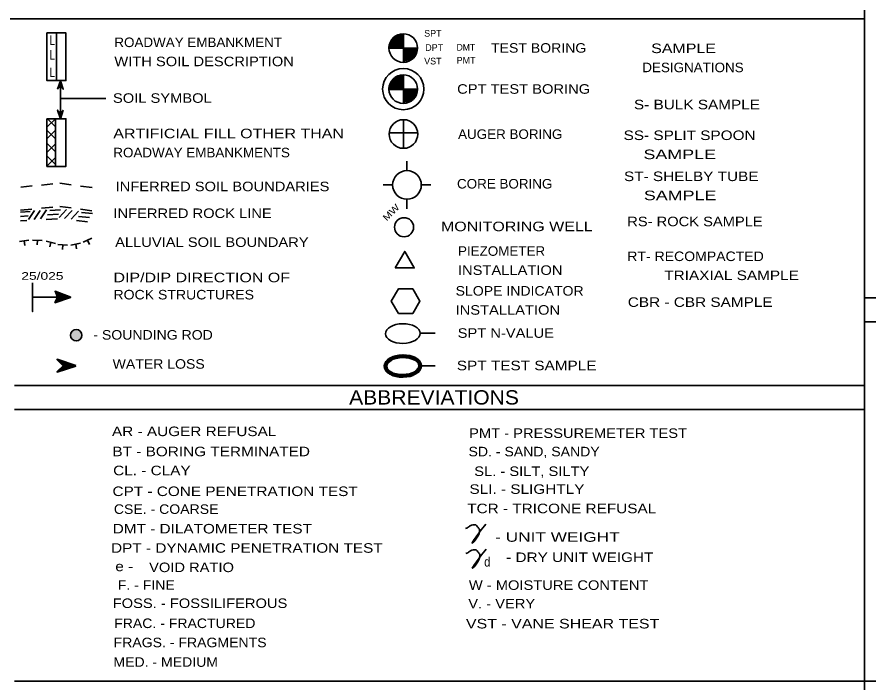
# Model space of a CAD drawing. Extents: x 2137492.6 to 2137529.1, y 2137475.8 to 2137563.
# Drawn here: x 2137501.9 to 2137510.82, y 2137544.13 to 2137551.11 of the extents above; entities that cross this region are included whole.
import ezdxf
from ezdxf.enums import TextEntityAlignment as Align

# ---------------------------------------------------------------- set-up
doc = ezdxf.new("R2010")
doc.units = 0
doc.header["$LTSCALE"] = 0.04
doc.linetypes.add('MEDIUM_DASHED', pattern=[4.5, 3, -1.5])
doc.layers.add('1', color=7, linetype='Continuous', lineweight=35)
doc.layers.add('10', color=7, linetype='Continuous', lineweight=40)

msp = doc.modelspace()

# ---------------------------------------------------------------- hatches: boundary and pattern name
at = {"layer": '1'}
for points in [[(2137502.32, 2137550.353), (2137502.35, 2137550.443), (2137502.38, 2137550.353), (2137502.35, 2137550.383)], [(2137502.38, 2137550.135), (2137502.35, 2137550.045), (2137502.32, 2137550.135), (2137502.35, 2137550.105)], [(2137502.57616, 2137547.77592, 1), (2137502.45616, 2137547.77592, 1)]]:
    msp.add_hatch(color=256, dxfattribs=at).paths.add_polyline_path(points)

# ---------------------------------------------------------------- linework, layer by layer
for p, q in [((2137510.771, 2137558.218), (2137510.771, 2137539.727)), ((2137510.771, 2137551.09), (2137493.171, 2137551.09)), ((2137502.308, 2137550.944), (2137502.308, 2137550.444)), ((2137505.942, 2137550.931), (2137505.942, 2137550.631)), ((2137505.922, 2137550.885), (2137505.865, 2137550.851)), ((2137506.092, 2137550.782), (2137505.792, 2137550.782)), ((2137505.942, 2137550.501), (2137505.942, 2137550.201)), ((2137505.922, 2137550.455), (2137505.865, 2137550.421)), ((2137506.092, 2137550.352), (2137505.792, 2137550.352)), ((2137502.35, 2137550.082), (2137502.35, 2137550.259)), ((2137502.209, 2137549.955), (2137502.295, 2137550.041)), ((2137502.295, 2137549.964), (2137502.214, 2137550.045)), ((2137502.297, 2137550.038), (2137502.297, 2137549.542)), ((2137505.942, 2137550.034), (2137505.942, 2137549.734)), ((2137502.207, 2137549.833), (2137502.297, 2137549.923)), ((2137502.291, 2137549.842), (2137502.209, 2137549.924)), ((2137506.092, 2137549.896), (2137505.792, 2137549.896)), ((2137502.209, 2137549.692), (2137502.297, 2137549.78)), ((2137502.291, 2137549.705), (2137502.211, 2137549.785)), ((2137502.21, 2137549.55), (2137502.298, 2137549.638)), ((2137502.296, 2137549.568), (2137502.211, 2137549.653)), ((2137505.979, 2137549.501), (2137505.979, 2137549.601)), ((2137505.829, 2137549.351), (2137505.729, 2137549.351)), ((2137506.129, 2137549.351), (2137506.229, 2137549.351)), ((2137505.979, 2137549.201), (2137505.979, 2137549.101)), ((2137501.932, 2137549.065), (2137502.033, 2137549.072)), ((2137502.016, 2137548.987), (2137502.079, 2137549.083)), ((2137502.076, 2137548.988), (2137502.138, 2137549.084)), ((2137502.142, 2137548.995), (2137502.204, 2137549.091)), ((2137502.214, 2137549.036), (2137502.331, 2137549.044)), ((2137502.238, 2137549.083), (2137502.352, 2137549.09)), ((2137502.336, 2137549.008), (2137502.414, 2137549.092)), ((2137502.393, 2137548.998), (2137502.472, 2137549.083)), ((2137502.462, 2137548.993), (2137502.538, 2137549.077)), ((2137502.571, 2137549.063), (2137502.685, 2137549.05)), ((2137501.932, 2137549.021), (2137502.012, 2137549.026)), ((2137501.932, 2137548.974), (2137501.998, 2137548.978)), ((2137502.202, 2137548.989), (2137502.318, 2137548.996)), ((2137502.519, 2137548.978), (2137502.634, 2137548.963)), ((2137502.538, 2137549.021), (2137502.656, 2137549.008)), ((2137501.921, 2137548.758), (2137502.02, 2137548.772)), ((2137502.059, 2137548.773), (2137502.159, 2137548.77)), ((2137502.108, 2137548.722), (2137502.109, 2137548.771)), ((2137502.588, 2137548.752), (2137502.68, 2137548.792)), ((2137502.654, 2137548.726), (2137502.634, 2137548.772)), ((2137501.978, 2137548.715), (2137501.971, 2137548.765)), ((2137502.202, 2137548.763), (2137502.299, 2137548.738)), ((2137502.238, 2137548.702), (2137502.251, 2137548.751)), ((2137502.324, 2137548.726), (2137502.424, 2137548.721)), ((2137502.372, 2137548.674), (2137502.374, 2137548.723)), ((2137502.461, 2137548.72), (2137502.559, 2137548.741)), ((2137502.52, 2137548.682), (2137502.51, 2137548.731)), ((2137510.771, 2137548.167), (2137519.912, 2137548.167)), ((2137510.771, 2137547.917), (2137519.912, 2137547.917)), ((2137506.117, 2137547.797), (2137506.275, 2137547.797)), ((2137506.117, 2137547.457), (2137506.275, 2137547.457)), ((2137501.871, 2137547.249), (2137510.771, 2137547.249)), ((2137501.871, 2137546.999), (2137510.771, 2137546.999)), ((2137519.912, 2137544.153), (2137501.871, 2137544.153))]:
    msp.add_line(p, q, dxfattribs=at)
for points in [[(2137502.208, 2137550.944), (2137502.408, 2137550.944), (2137502.408, 2137550.444), (2137502.208, 2137550.444)], [(2137502.308, 2137550.444), (2137502.408, 2137550.444), (2137502.408, 2137550.944), (2137502.308, 2137550.944)], [(2137502.32, 2137550.353), (2137502.35, 2137550.443), (2137502.38, 2137550.353), (2137502.35, 2137550.383)], [(2137502.38, 2137550.135), (2137502.35, 2137550.045), (2137502.32, 2137550.135), (2137502.35, 2137550.105)], [(2137502.208, 2137550.044), (2137502.408, 2137550.044), (2137502.408, 2137549.544), (2137502.208, 2137549.544)], [(2137505.855, 2137548.482), (2137506.055, 2137548.482), (2137505.955, 2137548.655)], [(2137505.89, 2137548.002), (2137506.04, 2137548.002), (2137506.115, 2137548.132), (2137506.04, 2137548.262), (2137505.89, 2137548.262), (2137505.815, 2137548.132)]]:
    msp.add_lwpolyline(points, close=True, dxfattribs=at)
for points in [[(2137505.788, 2137550.793), (2137505.935, 2137550.795), (2137505.788, 2137550.796), (2137505.796, 2137550.797), (2137505.935, 2137550.799), (2137505.788, 2137550.801), (2137505.934, 2137550.804), (2137505.79, 2137550.805), (2137505.934, 2137550.808), (2137505.789, 2137550.811), (2137505.935, 2137550.813), (2137505.792, 2137550.816), (2137505.935, 2137550.819), (2137505.793, 2137550.822), (2137505.934, 2137550.825), (2137505.793, 2137550.828), (2137505.935, 2137550.829), (2137505.797, 2137550.834), (2137505.935, 2137550.834), (2137505.798, 2137550.839), (2137505.935, 2137550.839), (2137505.8, 2137550.845), (2137505.936, 2137550.844), (2137505.804, 2137550.851), (2137505.935, 2137550.85), (2137505.807, 2137550.858), (2137505.936, 2137550.855), (2137505.813, 2137550.865), (2137505.936, 2137550.862), (2137505.816, 2137550.871), (2137505.935, 2137550.868), (2137505.822, 2137550.878), (2137505.935, 2137550.876), (2137505.828, 2137550.885), (2137505.935, 2137550.882), (2137505.834, 2137550.892), (2137505.937, 2137550.888), (2137505.843, 2137550.9), (2137505.935, 2137550.896), (2137505.853, 2137550.907), (2137505.935, 2137550.904), (2137505.866, 2137550.914), (2137505.935, 2137550.912), (2137505.883, 2137550.922), (2137505.934, 2137550.92), (2137505.904, 2137550.926), (2137505.935, 2137550.928), (2137505.92, 2137550.931)], [(2137506.088, 2137550.787), (2137505.941, 2137550.785), (2137506.088, 2137550.784), (2137506.08, 2137550.783), (2137505.941, 2137550.781), (2137506.088, 2137550.779), (2137505.942, 2137550.776), (2137506.086, 2137550.775), (2137505.942, 2137550.772), (2137506.087, 2137550.769), (2137505.941, 2137550.767), (2137506.084, 2137550.764), (2137505.941, 2137550.761), (2137506.083, 2137550.758), (2137505.942, 2137550.755), (2137506.083, 2137550.752), (2137505.941, 2137550.751), (2137506.079, 2137550.746), (2137505.941, 2137550.746), (2137506.078, 2137550.741), (2137505.941, 2137550.741), (2137506.076, 2137550.735), (2137505.94, 2137550.736), (2137506.072, 2137550.729), (2137505.941, 2137550.73), (2137506.069, 2137550.722), (2137505.94, 2137550.725), (2137506.063, 2137550.715), (2137505.94, 2137550.718), (2137506.06, 2137550.709), (2137505.941, 2137550.712), (2137506.054, 2137550.702), (2137505.941, 2137550.704), (2137506.048, 2137550.695), (2137505.941, 2137550.698), (2137506.042, 2137550.688), (2137505.939, 2137550.692), (2137506.033, 2137550.68), (2137505.941, 2137550.684), (2137506.023, 2137550.673), (2137505.941, 2137550.676), (2137506.01, 2137550.666), (2137505.941, 2137550.668), (2137505.993, 2137550.658), (2137505.942, 2137550.66), (2137505.972, 2137550.654), (2137505.941, 2137550.652), (2137505.956, 2137550.649)], [(2137505.788, 2137550.363), (2137505.935, 2137550.365), (2137505.788, 2137550.366), (2137505.796, 2137550.367), (2137505.935, 2137550.369), (2137505.788, 2137550.371), (2137505.934, 2137550.374), (2137505.79, 2137550.375), (2137505.934, 2137550.378), (2137505.789, 2137550.381), (2137505.935, 2137550.383), (2137505.792, 2137550.386), (2137505.935, 2137550.389), (2137505.793, 2137550.392), (2137505.934, 2137550.395), (2137505.793, 2137550.398), (2137505.935, 2137550.399), (2137505.797, 2137550.404), (2137505.935, 2137550.404), (2137505.798, 2137550.409), (2137505.935, 2137550.409), (2137505.8, 2137550.415), (2137505.936, 2137550.414), (2137505.804, 2137550.421), (2137505.935, 2137550.42), (2137505.807, 2137550.428), (2137505.936, 2137550.425), (2137505.813, 2137550.435), (2137505.936, 2137550.432), (2137505.816, 2137550.441), (2137505.935, 2137550.438), (2137505.822, 2137550.448), (2137505.935, 2137550.446), (2137505.828, 2137550.455), (2137505.935, 2137550.452), (2137505.834, 2137550.462), (2137505.937, 2137550.458), (2137505.843, 2137550.47), (2137505.935, 2137550.466), (2137505.853, 2137550.477), (2137505.935, 2137550.474), (2137505.866, 2137550.484), (2137505.935, 2137550.482), (2137505.883, 2137550.492), (2137505.934, 2137550.49), (2137505.904, 2137550.496), (2137505.935, 2137550.498), (2137505.92, 2137550.501)], [(2137502.35, 2137550.392), (2137502.35, 2137550.258), (2137502.827, 2137550.258)], [(2137506.088, 2137550.357), (2137505.941, 2137550.355), (2137506.088, 2137550.354), (2137506.08, 2137550.353), (2137505.941, 2137550.351), (2137506.088, 2137550.349), (2137505.942, 2137550.346), (2137506.086, 2137550.345), (2137505.942, 2137550.342), (2137506.087, 2137550.339), (2137505.941, 2137550.337), (2137506.084, 2137550.334), (2137505.941, 2137550.331), (2137506.083, 2137550.328), (2137505.942, 2137550.325), (2137506.083, 2137550.322), (2137505.941, 2137550.321), (2137506.079, 2137550.316), (2137505.941, 2137550.316), (2137506.078, 2137550.311), (2137505.941, 2137550.311), (2137506.076, 2137550.305), (2137505.94, 2137550.306), (2137506.072, 2137550.299), (2137505.941, 2137550.3), (2137506.069, 2137550.292), (2137505.94, 2137550.295), (2137506.063, 2137550.285), (2137505.94, 2137550.288), (2137506.06, 2137550.279), (2137505.941, 2137550.282), (2137506.054, 2137550.272), (2137505.941, 2137550.274), (2137506.048, 2137550.265), (2137505.941, 2137550.268), (2137506.042, 2137550.258), (2137505.939, 2137550.262), (2137506.033, 2137550.25), (2137505.941, 2137550.254), (2137506.023, 2137550.243), (2137505.941, 2137550.246), (2137506.01, 2137550.236), (2137505.941, 2137550.238), (2137505.993, 2137550.228), (2137505.942, 2137550.23), (2137505.972, 2137550.224), (2137505.941, 2137550.222), (2137505.956, 2137550.219)], [(2137502.058, 2137548.324), (2137502.058, 2137548.024), (2137502.058, 2137548.174), (2137502.458, 2137548.174), (2137502.295, 2137548.237), (2137502.32, 2137548.174), (2137502.296, 2137548.122), (2137502.293, 2137548.116), (2137502.456, 2137548.173), (2137502.324, 2137548.171), (2137502.299, 2137548.12), (2137502.441, 2137548.169), (2137502.354, 2137548.169), (2137502.325, 2137548.168), (2137502.304, 2137548.125), (2137502.427, 2137548.167), (2137502.328, 2137548.167), (2137502.311, 2137548.13), (2137502.418, 2137548.167), (2137502.319, 2137548.163), (2137502.331, 2137548.161), (2137502.314, 2137548.132), (2137502.332, 2137548.167), (2137502.406, 2137548.163), (2137502.32, 2137548.135), (2137502.336, 2137548.162), (2137502.396, 2137548.162), (2137502.326, 2137548.141), (2137502.337, 2137548.16), (2137502.38, 2137548.16), (2137502.333, 2137548.145), (2137502.338, 2137548.159), (2137502.364, 2137548.159), (2137502.339, 2137548.15), (2137502.342, 2137548.156), (2137502.354, 2137548.155), (2137502.345, 2137548.153), (2137502.325, 2137548.144), (2137502.331, 2137548.157), (2137502.32, 2137548.136), (2137502.308, 2137548.13), (2137502.324, 2137548.163), (2137502.313, 2137548.202), (2137502.3, 2137548.231), (2137502.447, 2137548.176), (2137502.322, 2137548.178), (2137502.437, 2137548.18), (2137502.306, 2137548.227), (2137502.324, 2137548.176), (2137502.421, 2137548.181), (2137502.326, 2137548.181), (2137502.312, 2137548.222), (2137502.319, 2137548.217), (2137502.326, 2137548.184), (2137502.323, 2137548.217), (2137502.423, 2137548.182), (2137502.329, 2137548.184), (2137502.325, 2137548.211), (2137502.409, 2137548.186), (2137502.331, 2137548.187), (2137502.397, 2137548.187), (2137502.328, 2137548.208), (2137502.385, 2137548.187), (2137502.326, 2137548.204), (2137502.332, 2137548.191), (2137502.372, 2137548.186), (2137502.341, 2137548.193), (2137502.328, 2137548.192), (2137502.33, 2137548.198), (2137502.373, 2137548.19), (2137502.332, 2137548.2), (2137502.324, 2137548.216), (2137502.367, 2137548.199), (2137502.312, 2137548.221), (2137502.326, 2137548.205), (2137502.316, 2137548.215), (2137502.32, 2137548.208), (2137502.322, 2137548.203)]]:
    msp.add_lwpolyline(points, dxfattribs=at)
at = {"layer": '1', "linetype": 'MEDIUM_DASHED'}
for points in [[(2137501.934, 2137549.329), (2137502.344, 2137549.368), (2137502.698, 2137549.32)], [(2137501.933, 2137549.087), (2137502.343, 2137549.126), (2137502.697, 2137549.078)]]:
    msp.add_lwpolyline(points, dxfattribs=at)
at = {"layer": '1'}
for centre, radius in [((2137505.94006, 2137550.78486), 0.15), ((2137505.94006, 2137550.3545), 0.216), ((2137505.94006, 2137550.3545), 0.15), ((2137505.94206, 2137549.88431), 0.15), ((2137505.979, 2137549.35045), 0.15), ((2137505.94806, 2137548.90777), 0.1), ((2137502.51616, 2137547.77592), 0.06)]:
    msp.add_circle(centre, radius, dxfattribs=at)
msp.add_ellipse((2137505.93556, 2137547.79336), major_axis=(0.1815, 0.0025), ratio=0.568627, dxfattribs=at)
at = {"layer": '1', "lineweight": 100}
msp.add_ellipse((2137505.93556, 2137547.45328), major_axis=(0.1815, 0.0025), ratio=0.568627, dxfattribs=at)
at = {"layer": '1'}
for points in [[(2137506.593, 2137545.75), (2137506.612, 2137545.759), (2137506.641, 2137545.779), (2137506.67, 2137545.788), (2137506.699, 2137545.788), (2137506.718, 2137545.769), (2137506.737, 2137545.74), (2137506.66, 2137545.596), (2137506.737, 2137545.711), (2137506.805, 2137545.798)], [(2137506.596, 2137545.488), (2137506.615, 2137545.497), (2137506.644, 2137545.517), (2137506.673, 2137545.526), (2137506.702, 2137545.526), (2137506.721, 2137545.507), (2137506.74, 2137545.478), (2137506.663, 2137545.334), (2137506.74, 2137545.449), (2137506.808, 2137545.536)]]:
    msp.add_spline(points, degree=3, dxfattribs=at)
at = {"layer": '10'}
for p, q in [((2137502.322, 2137547.515), (2137502.324, 2137547.518)), ((2137502.327, 2137547.396), (2137502.418, 2137547.487)), ((2137502.328, 2137547.51), (2137502.333, 2137547.515)), ((2137502.333, 2137547.504), (2137502.341, 2137547.512)), ((2137502.339, 2137547.498), (2137502.35, 2137547.509)), ((2137502.343, 2137547.401), (2137502.426, 2137547.484)), ((2137502.345, 2137547.493), (2137502.358, 2137547.507)), ((2137502.35, 2137547.487), (2137502.367, 2137547.504)), ((2137502.356, 2137547.481), (2137502.375, 2137547.501)), ((2137502.36, 2137547.406), (2137502.435, 2137547.481)), ((2137502.362, 2137547.476), (2137502.384, 2137547.498)), ((2137502.367, 2137547.47), (2137502.392, 2137547.495)), ((2137502.373, 2137547.464), (2137502.401, 2137547.493)), ((2137502.377, 2137547.412), (2137502.443, 2137547.478)), ((2137502.379, 2137547.459), (2137502.409, 2137547.49)), ((2137502.393, 2137547.417), (2137502.452, 2137547.476)), ((2137502.41, 2137547.422), (2137502.46, 2137547.473)), ((2137502.427, 2137547.428), (2137502.469, 2137547.47)), ((2137502.443, 2137547.433), (2137502.477, 2137547.467)), ((2137502.46, 2137547.438), (2137502.486, 2137547.464)), ((2137502.476, 2137547.443), (2137502.494, 2137547.462)), ((2137502.493, 2137547.449), (2137502.503, 2137547.459)), ((2137502.51, 2137547.454), (2137502.511, 2137547.456))]:
    msp.add_line(p, q, dxfattribs=at)
msp.add_lwpolyline([(2137502.511, 2137547.457), (2137502.317, 2137547.521), (2137502.381, 2137547.457), (2137502.317, 2137547.393), (2137502.511, 2137547.455)], dxfattribs=at)

# ---------------------------------------------------------------- texts
at = {"layer": '1'}
for s, height, width, p in [('L', 0.1, 0.75, (2137502.265, 2137550.817)), ('TEST BORING', 0.1, 1.1, (2137507.3575, 2137550.736)), ('L', 0.1, 0.75, (2137502.265, 2137550.663)), ('L', 0.1, 0.75, (2137502.265, 2137550.481)), ('CPT TEST BORING', 0.1, 1.15, (2137507.2005, 2137550.306)), ('SOIL SYMBOL', 0.1, 1.15, (2137503.4175, 2137550.211)), ('S- BULK SAMPLE', 0.1, 1.2, (2137509.015, 2137550.143)), ('AUGER BORING', 0.1, 1.05, (2137507.06, 2137549.833)), ('CORE BORING', 0.1, 1.05, (2137507.002, 2137549.313)), ('INFERRED SOIL BOUNDARIES', 0.1, 1.15, (2137504.0475, 2137549.285)), ('INFERRED ROCK LINE', 0.1, 1.15, (2137503.734, 2137549.004)), ('   MONITORING WELL', 0.1, 1.25, (2137507.059, 2137548.866)), ('ALLUVIAL SOIL BOUNDARY', 0.1, 1.15, (2137503.936, 2137548.701)), ('25/025', 0.08, 1.35, (2137502.1615, 2137548.357)), ('- SOUNDING ROD', 0.1, 1.1, (2137503.3205, 2137547.73)), ('SPT N-VALUE', 0.1, 1.15, (2137507.014, 2137547.749)), ('WATER LOSS', 0.1, 1.1, (2137503.379, 2137547.425)), ('SPT TEST SAMPLE', 0.1, 1.2, (2137507.232, 2137547.409)), ('AR - AUGER REFUSAL', 0.1, 1.2, (2137503.7505, 2137546.719)), ('PMT - PRESSUREMETER TEST', 0.1, 1.15, (2137507.7705, 2137546.7)), ('BT - BORING TERMINATED', 0.1, 1.2, (2137503.929, 2137546.508)), ('SD. - SAND, SANDY', 0.1, 1.1, (2137507.31, 2137546.507)), ('CL. - CLAY', 0.1, 1.2, (2137503.308, 2137546.309)), ('SL. - SILT, SILTY', 0.1, 1.15, (2137507.2855, 2137546.301)), ('CPT - CONE PENETRATION TEST', 0.1, 1.2, (2137504.1795, 2137546.091)), ('SLI. - SLIGHTLY', 0.1, 1.2, (2137507.235, 2137546.114)), ('CSE. - COARSE', 0.1, 1.1, (2137503.4575, 2137545.904)), ('TCR - TRICONE REFUSAL', 0.1, 1.2, (2137507.599, 2137545.911)), ('DMT - DILATOMETER TEST', 0.1, 1.2, (2137503.941, 2137545.699)), ('  - UNIT WEIGHT ', 0.1, 1.35, (2137507.529, 2137545.612)), ('DPT - DYNAMIC PENETRATION TEST', 0.1, 1.2, (2137504.3025, 2137545.497)), ('- DRY UNIT WEIGHT', 0.1, 1.2, (2137507.788, 2137545.4)), ('e -', 0.1, 1.2, (2137503.0185, 2137545.304)), ('VOID RATIO', 0.1, 1.15, (2137503.723, 2137545.294)), ('d', 0.1, 0.85, (2137506.8195, 2137545.352)), ('F. - FINE', 0.1, 1.1, (2137503.249, 2137545.109)), ('W - MOISTURE CONTENT', 0.1, 1.15, (2137507.5665, 2137545.108)), ('FOSS. - FOSSILIFEROUS', 0.1, 1.15, (2137503.812, 2137544.918)), ('V. - VERY', 0.1, 1.15, (2137506.971, 2137544.914)), ('FRAC. - FRACTURED', 0.1, 1.1, (2137503.6525, 2137544.708)), ('VST - VANE SHEAR TEST', 0.1, 1.25, (2137507.6085, 2137544.704)), ('FRAGS. - FRAGMENTS', 0.1, 1.1, (2137503.708, 2137544.507)), ('MED. - MEDIUM', 0.1, 1.1, (2137503.4525, 2137544.302))]:
    msp.add_text(s, height=height, dxfattribs=dict(at, width=width)).set_placement(p, align=Align.CENTER)
for s, p in [('SPT', (2137506.159, 2137550.904)), ('DPT', (2137506.17, 2137550.755)), ('VST', (2137506.159, 2137550.613)), ('PMT', (2137506.499, 2137550.621))]:
    msp.add_text(s, height=0.07, dxfattribs=at).set_placement(p)
for s, height, width, p in [('ROADWAY EMBANKMENT', 0.1, 1.05, (2137502.915, 2137550.795)), ('DMT', 0.07, 0.95, (2137506.499, 2137550.758)), ('  SAMPLE', 0.1, 1.25, (2137508.443, 2137550.732)), ('WITH SOIL DESCRIPTION', 0.1, 1.15, (2137502.915, 2137550.595)), ('DESIGNATIONS', 0.1, 1.05, (2137508.443, 2137550.532)), ('ARTIFICIAL FILL OTHER THAN', 0.1, 1.25, (2137502.904, 2137549.84)), ('SS- SPLIT SPOON', 0.1, 1.2, (2137508.247, 2137549.821)), ('ROADWAY EMBANKMENTS', 0.1, 1.05, (2137502.904, 2137549.64)), ('    SAMPLE', 0.1, 1.4, (2137508.247, 2137549.621)), ('ST- SHELBY TUBE', 0.1, 1.2, (2137508.251, 2137549.391)), ('    SAMPLE', 0.1, 1.4, (2137508.251, 2137549.191)), ('RS- ROCK SAMPLE', 0.1, 1.15, (2137508.285, 2137548.918)), ('PIEZOMETER', 0.1, 1.05, (2137506.513, 2137548.608)), ('RT- RECOMPACTED', 0.1, 1.1, (2137508.285, 2137548.553)), ('INSTALLATION', 0.1, 1.15, (2137506.513, 2137548.408)), ('DIP/DIP DIRECTION OF ', 0.1, 1.25, (2137502.906, 2137548.331)), ('TRIAXIAL SAMPLE', 0.1, 1.2, (2137508.673, 2137548.354)), ('ROCK STRUCTURES', 0.1, 1.1, (2137502.906, 2137548.151)), ('SLOPE INDICATOR', 0.1, 1.1, (2137506.488, 2137548.191)), ('CBR - CBR SAMPLE', 0.1, 1.2, (2137508.291, 2137548.073)), ('INSTALLATION', 0.1, 1.15, (2137506.488, 2137547.991)), ('ABBREVIATIONS', 0.15, 1.1, (2137505.373, 2137547.05))]:
    msp.add_text(s, height=height, dxfattribs=dict(at, width=width)).set_placement(p)
at = {"layer": '1', "width": 1.2}
msp.add_text('MW', height=0.07, rotation=45, dxfattribs=at).set_placement((2137505.767, 2137548.967))

doc.saveas('drawing.dxf')
